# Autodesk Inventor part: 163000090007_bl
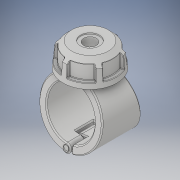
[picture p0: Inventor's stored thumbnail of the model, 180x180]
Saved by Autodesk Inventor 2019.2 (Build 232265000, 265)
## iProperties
Created: 2022-02
Part Number: 163000090007_bl
Material: Generic
Description: Plassadle Threaded 90x3/4''
Document SubType Name: Modeling
Designer: comp2
Density: 1 g/cm^3
Appearance: Default
Author: comp2
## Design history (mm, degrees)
derived "16300.ipt"
feature "Solid1::16300.ipt" dims "ScaleForDerivedMember" = 10
feature "Solid2::16300.ipt" dims "ScaleForDerivedMember" = 10
feature "Solid3::16300.ipt" dims "ScaleForDerivedMember" = 10
feature "Solid4::16300.ipt" dims "ScaleForDerivedMember" = 10
tag "TaggingFeature1"
body "Solid1"
body "Solid2"
body "Solid3"
body "Solid4"
other parameters: "d2" = 119 [user parameter], "d3" = 45 [user parameter], "d7" = 113.05 [user parameter], "d8" = 85 deg [user parameter], "d9" = 45 deg [user parameter], "d10" = 102 [user parameter], "d11" = 49 [user parameter], "d12" = 31.2165 [user parameter], "d13" = 42.84 [user parameter], "d14" = 36.1755 [user parameter], "d42" = 2.9 [user parameter], "d49" = 2.38 [user parameter], "d50" = 94 [user parameter], "d51" = 0 [user parameter], "d52" = 20.3 [user parameter], "d53" = 65.45 [user parameter], "d54" = 32.9 [user parameter], "d55" = 0 [user parameter], "d56" = 18.8 [user parameter], "d57" = 18.8 [user parameter], "d59" = 0 [user parameter], "d60" = 94 [user parameter], "d61" = 0 [user parameter], "d62" = 32.9 [user parameter], "d63" = 0 [user parameter], "d65" = 0 [user parameter], "d67" = 0 [user parameter], "d69" = 0 [user parameter], "d70" = 1 [user parameter], "d71" = 90.24 [user parameter], "d72" = 0 [user parameter], "d73" = 2 [user parameter], "d78" = 86.7 [user parameter], "d79" = 5.1 [user parameter], "d80" = 60 deg [user parameter], "d81" = 5.1 [user parameter], "d84" = 0 [user parameter], "d85" = 1 [user parameter], "d87" = 360 deg [user parameter], "d122" = 49 [user parameter], "d124" = 42.80128 [user parameter], "d125" = 2.22975 [user parameter], "d127" = 163 [user parameter], "d129" = 24.117 [user parameter], "d130" = 20.49945 [user parameter], "d131" = 31.85 [user parameter], "d132" = 45 deg [user parameter], "d133" = 22.295 [user parameter], "d134" = 12.0585 [user parameter], "d136" = 0 [user parameter], "d138" = 0 [user parameter], "d1" = 25 [user parameter], "B" = 119 [user parameter], "L" = 94 [user parameter], "E_" = 54 [user parameter], "E1" = 102 [user parameter], "H1" = 163 [user parameter], "H2" = 49 [user parameter], "H3" = 78 [user parameter], "H_costum" = 49 [user parameter], "Rp" = 24.117 [user parameter], "d128" = 44.595 [user parameter]
